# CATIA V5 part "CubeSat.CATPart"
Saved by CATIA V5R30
Part number: CubeSat V2
Bounding box of the stored display mesh (mm): x -50 to 50, y -50 to 50, z 0 to 99
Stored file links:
  D:\OneDrive\OneDrive - Carleton University\Courses\aero2001\Design Project\3D Models\CubeSat V2.CATPart
  D:\OneDrive\OneDrive - Carleton University\Courses\aero2001\Design Project\3D Models\Hatch.CATPart
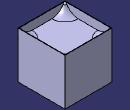
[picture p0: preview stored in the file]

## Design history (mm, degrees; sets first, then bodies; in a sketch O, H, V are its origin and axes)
Body1 (main body)
  Sketch1 on xy-plane, origin (0, 0, 0), H (1, 0, 0), V (0, 1, 0)
    line L1 (50, 50) -> (50, -50)
    line L2 (50, -50) -> (-50, -50)
    line L3 (-50, -50) -> (-50, 50)
    line L4 (-50, 50) -> (50, 50)
    distance L2 L4 = 100
    distance L1 L3 = 100
    vertical: L1 V, L3 V
    horizontal: L2 H, L4 H
    equidistance: L1 L3 O, L2 L4 O
  Pad1: profile Sketch1, direction (0, 0, 1), length 99
  Shell1: ExtOffset 0, Face end face of Pad1, IntOffset 1
  Plane1: type Offset, RefPlane face of Shell1, Offset 80, reversed
  DatumCurve1
  DatumCurve2
  Sketch2 on Plane1, origin (0, 0, 81), H (1, 0, 0), V (0, -1, 0)
    line L1 (50, 50) -> (50, -50)
    line L2 (50, -50) -> (-50, -50)
    line L3 (-50, -50) -> (-50, 50)
    line L4 (-50, 50) -> (50, 50)
    distance L2 L4 = 100
    distance L1 L3 = 100
    vertical: L1 V, L3 V
    horizontal: L2 H, L4 H
    equidistance: L1 L3 O, L2 L4 O
  Pad2: profile Sketch2, direction (0, 0, -1), length 1
  Sketch3 on face of Shell1, origin (0, 49, 0), H (1, 0, 0), V (0, 0, 1)
    point P1 (21, 81)
    line L1 (21, 81) -> (49, 81)
    line L2 (49, 81) -> (49, 99)
    point P3 (49, 99)
    reference projected line E1 (49, 1) -> (49, 99) from edge [face of Shell1 | face of Shell1]
    reference projected line E2 (-49, 81) -> (49, 81) from edge [start face of Pad2 | face of Shell1]
    spline S1 through (21, 81) (35.3112, 85.5728) (45.0537, 95.8544)
    spline S2 through (45.0537, 95.8544) (46.6325, 97.9723) (49, 99)
    reference projected line E3 (-50, 99) -> (50, 99) from edge [face of Pad2 | end face of Pad1]
    point P4 (21, 81)
    point P5 (45.0537, 95.8544)
    point P6 (45.0537, 95.8544)
    point P7 (49, 99)
    length L1 = 28
    horizontal: L1 H
    vertical: L2 V
    coincidence: E1 L2, L1 E2, P4 P1, P5 P6, P3 P7, P7 E3
  Shaft1: profile Sketch3, axis Sketch3.L2, angle 90
  Point1: (0, 0, 0)
  Line1: type Normal, RefPoint Point1, RefSkin xy-plane, Start 0, End 20
  CircPattern1: of Shaft1, instances 4, angular step 90 {= 360.0*1 deg/CircPattern1.AngularNumber}, axis from Line1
